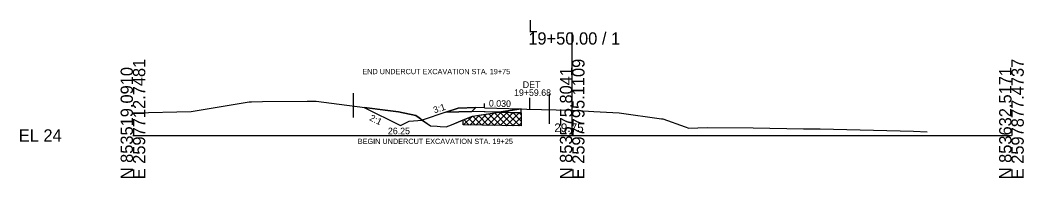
# Model space of a CAD drawing. Extents: x -26 to 1203, y -10 to 9526.
# Drawn here: x -25.7 to 202.8, y 9490.3 to 9526.3 of the extents above; entities that cross this region are included whole.
import ezdxf

# ---------------------------------------------------------------- set-up
doc = ezdxf.new("R2010")
doc.units = 0
for name, color, linetype in [('Exist Cross Section Cell', 7, 'Continuous'), ('Exist XS Center Line Elevation Label', 7, 'Continuous'), ('Exist XS Ground Line', 7, 'Continuous'), ('Prop XS Alignment Label', 7, 'Continuous'), ('Prop XS DDE', 7, 'Continuous'), ('Prop XS DDE Earthwork Shape', 7, 'Continuous'), ('Prop XS DDE Elevations', 7, 'Continuous'), ('Prop XS DDE Slope Text', 7, 'Continuous'), ('Prop XS Earthwork Shape', 7, 'Continuous'), ('Prop XS EOT Tick Mark', 7, 'Continuous'), ('Prop XS Exc Vertical Line 1', 7, 'Continuous'), ('Prop XS Exc Vertical Line 2', 7, 'Continuous'), ('Prop XS Finish Grade', 7, 'Continuous'), ('Prop XS Finish Grade Earthwork', 7, 'Continuous'), ('Prop XS Finish Grade Paved Shoulder', 7, 'Continuous'), ('Prop XS Finish Grade Pavement', 7, 'Continuous'), ('Prop XS Pvmt Edge Slope', 7, 'Continuous'), ('Prop XS SE Text', 7, 'Continuous'), ('Prop XS Side Slope Text', 7, 'Continuous'), ('Prop XS Station Labels', 7, 'Continuous'), ('Prop XS Subgrade Earthwork', 7, 'Continuous'), ('Prop XS Undercut Exc', 7, 'Continuous'), ('Prop XS Undercut Exc Hatch', 7, 'Continuous'), ('Scratch_Level_1', 7, 'Continuous')]:
    doc.layers.add(name, color=color, linetype=linetype)

msp = doc.modelspace()

# ---------------------------------------------------------------- linework, layer by layer
at = {"layer": 'Exist Cross Section Cell'}
for p, q in [((100, 9500), (100, 9523.51)), ((0, 9500), (100, 9500)), ((100, 9500), (200, 9500))]:
    msp.add_line(p, q, dxfattribs=at)
at = {"layer": 'Exist XS Ground Line'}
for p, q in [((13.26, 9505.49), (26.43, 9507.64)), ((26.43, 9507.64), (27.01, 9507.7)), ((27.01, 9507.7), (29.49, 9507.73)), ((29.49, 9507.73), (39.69, 9507.84)), ((39.69, 9507.84), (41.72, 9507.78)), ((41.72, 9507.78), (58.03, 9505.69)), ((0, 9505.12), (0.29, 9505.12)), ((0.29, 9505.12), (13.26, 9505.49)), ((58.03, 9505.69), (60.43, 9505.37)), ((60.43, 9505.37), (64.38, 9504.53)), ((77.27, 9504.39), (79.43, 9504.72)), ((79.43, 9504.72), (88.37, 9506.06)), ((88.37, 9506.06), (89.64, 9506.02)), ((89.64, 9506.02), (99.67, 9505.77)), ((99.67, 9505.77), (100, 9505.75)), ((100, 9505.75), (104.89, 9505.49)), ((104.89, 9505.49), (110.73, 9505.18)), ((110.73, 9505.18), (120.33, 9503.82)), ((64.38, 9504.53), (65.15, 9504.01)), ((65.15, 9504.01), (67.77, 9502.18)), ((71.3, 9501.96), (72.49, 9502.42)), ((72.49, 9502.42), (77.27, 9504.39)), ((120.33, 9503.82), (120.65, 9503.78)), ((120.65, 9503.78), (125.72, 9501.95)), ((67.77, 9502.18), (69.25, 9502.08)), ((69.25, 9502.08), (69.97, 9502.03)), ((69.97, 9502.03), (71.3, 9501.96)), ((125.72, 9501.95), (126.54, 9501.67)), ((126.54, 9501.67), (128.59, 9501.76)), ((128.59, 9501.76), (130.81, 9501.82)), ((130.81, 9501.82), (141.2, 9501.71)), ((141.2, 9501.71), (152.66, 9501.53)), ((152.66, 9501.53), (156.49, 9501.5)), ((156.49, 9501.5), (177.69, 9500.95)), ((177.69, 9500.95), (180.78, 9500.85))]:
    msp.add_line(p, q, dxfattribs=at)
at = {"layer": 'Prop XS DDE'}
for p, q in [((52.62, 9506.38), (60.88, 9502.25)), ((60.88, 9502.25), (62.88, 9503.25)), ((62.88, 9503.25), (65.88, 9503.5))]:
    msp.add_line(p, q, dxfattribs=at)
at = {"layer": 'Prop XS DDE Earthwork Shape'}
for p, q in [((58.03, 9505.69), (52.62, 9506.38)), ((52.62, 9506.38), (60.88, 9502.25)), ((60.43, 9505.37), (58.03, 9505.69)), ((64.38, 9504.53), (60.43, 9505.37)), ((60.88, 9502.25), (62.88, 9503.25)), ((62.88, 9503.25), (65.88, 9503.5)), ((65.15, 9504.01), (64.38, 9504.53)), ((65.88, 9503.5), (65.15, 9504.01))]:
    msp.add_line(p, q, dxfattribs=at)
at = {"layer": 'Prop XS Earthwork Shape'}
for points in [[(77.18, 9505.47), (71.2, 9505.27), (65.88, 9503.5), (67.77, 9502.18), (69.25, 9502.08), (69.97, 9502.03), (71.3, 9501.96), (72.49, 9502.42), (75.18, 9503.53), (77.27, 9504.39), (79.43, 9504.72), (83.3, 9505.3)], [(75.18, 9502.4), (75.18, 9503.53), (77.27, 9504.39), (79.43, 9504.72), (83.3, 9505.3), (88.37, 9505.16), (88.37, 9502.16)], [(88.37, 9505.16), (88.37, 9506.06), (83.3, 9505.3)]]:
    msp.add_lwpolyline(points, close=True, dxfattribs=at)
at = {"layer": 'Prop XS EOT Tick Mark'}
msp.add_line((80.07, 9506.3), (80.07, 9507.3), dxfattribs=at)
at = {"layer": 'Prop XS Exc Vertical Line 1'}
msp.add_line((50.11, 9509.65), (50.11, 9504.07), dxfattribs=at)
at = {"layer": 'Prop XS Exc Vertical Line 2'}
msp.add_line((94.75, 9509.5), (94.75, 9502.68), dxfattribs=at)
at = {"layer": 'Prop XS Finish Grade'}
for p in [(71.2, 9505.27), (78.07, 9506.36)]:
    msp.add_line(p, (74.07, 9506.23), dxfattribs=at)
at = {"layer": 'Prop XS Finish Grade Earthwork'}
msp.add_line((71.2, 9505.27), (65.88, 9503.5), dxfattribs=at)
at = {"layer": 'Prop XS Finish Grade Paved Shoulder'}
msp.add_line((80.07, 9506.3), (78.07, 9506.36), dxfattribs=at)
at = {"layer": 'Prop XS Finish Grade Pavement'}
msp.add_line((80.07, 9506.3), (88.37, 9506.06), dxfattribs=at)
at = {"layer": 'Prop XS Pvmt Edge Slope'}
msp.add_line((78.07, 9506.36), (77.18, 9505.47), dxfattribs=at)
at = {"layer": 'Prop XS Side Slope Text'}
msp.add_line((90.25, 9508.6), (90.25, 9506.08), dxfattribs=at)
at = {"layer": 'Prop XS Subgrade Earthwork'}
for p, q in [((77.18, 9505.47), (71.2, 9505.27)), ((88.37, 9505.16), (77.18, 9505.47)), ((88.37, 9505.16), (88.37, 9506.06))]:
    msp.add_line(p, q, dxfattribs=at)
at = {"layer": 'Prop XS Undercut Exc'}
for p, q in [((88.37, 9505.16), (88.37, 9502.16)), ((75.18, 9502.4), (75.18, 9503.53)), ((88.37, 9502.16), (75.18, 9502.4))]:
    msp.add_line(p, q, dxfattribs=at)
at = {"layer": 'Prop XS Undercut Exc Hatch'}
for p, q in [((78.05, 9502.35), (80.6, 9504.89)), ((79.44, 9502.32), (82.26, 9505.14)), ((79.82, 9504.77), (82.33, 9502.27)), ((80.83, 9502.3), (83.82, 9505.28)), ((81.05, 9504.96), (83.77, 9502.24)), ((82.22, 9502.27), (85.19, 9505.24)), ((82.28, 9505.14), (85.21, 9502.21)), ((83.55, 9505.29), (86.65, 9502.19)), ((83.61, 9502.24), (86.57, 9505.21)), ((85, 9505.25), (88.09, 9502.16)), ((85, 9502.22), (87.94, 9505.17)), ((86.46, 9505.21), (88.37, 9503.29)), ((87.91, 9505.17), (88.37, 9504.71)), ((75.28, 9502.4), (77.27, 9504.39)), ((75.34, 9503.6), (76.56, 9502.38)), ((76.34, 9504.01), (78, 9502.35)), ((76.67, 9502.37), (78.93, 9504.64)), ((77.36, 9504.41), (79.44, 9502.32)), ((78.59, 9504.59), (80.88, 9502.3)), ((86.38, 9502.19), (88.37, 9504.18)), ((87.77, 9502.17), (88.37, 9502.77))]:
    msp.add_line(p, q, dxfattribs=at)
msp.add_lwpolyline([(88.37, 9502.16), (75.18, 9502.4), (75.18, 9503.53), (77.27, 9504.39), (83.3, 9505.3), (88.37, 9505.16)], close=True, dxfattribs=at)
at = {"layer": 'Scratch_Level_1'}
for points in [[(77.18, 9505.47), (71.2, 9505.27), (74.07, 9506.23), (78.07, 9506.36)], [(78.07, 9506.36), (74.07, 9506.23), (71.2, 9505.27), (77.18, 9505.47)]]:
    msp.add_lwpolyline(points, close=True, dxfattribs=at)

# ---------------------------------------------------------------- texts
at = {"layer": 'Exist Cross Section Cell'}
for s, p in [('L', (90, 9523.51)), ('19+50.00 / 1', (90, 9520.71)), ('EL 24', (-26, 9498.6))]:
    msp.add_text(s, height=2.8, dxfattribs=at).set_placement(p)
for s, p in [('E 2597712.7481', (2.8, 9490)), ('E 2597795.1109', (102.8, 9490)), ('E 2597877.4737', (202.8, 9490)), ('N 853519.0910', (0, 9490)), ('N 853575.8041', (100, 9490)), ('N 853632.5171', (200, 9490))]:
    msp.add_text(s, height=2.8, rotation=90, dxfattribs=at).set_placement(p)
at = {"layer": 'Exist XS Center Line Elevation Label'}
msp.add_text('29.75', height=2, dxfattribs=at).set_placement((95.93, 9500.75))
at = {"layer": 'Prop XS Alignment Label'}
msp.add_text('DET', height=1.5, dxfattribs=at).set_placement((88.75, 9510.83))
at = {"layer": 'Prop XS DDE Elevations'}
msp.add_text('26.25', height=1.5, dxfattribs=at).set_placement((58.05, 9500.28))
at = {"layer": 'Prop XS DDE Slope Text'}
msp.add_text('2:1', height=1.5, rotation=333.4349, dxfattribs=at).set_placement((53.71, 9503.52))
at = {"layer": 'Prop XS SE Text'}
msp.add_text('0.030', height=1.5, rotation=358.4069, dxfattribs=at).set_placement((81.02, 9506.61))
at = {"layer": 'Prop XS Side Slope Text'}
msp.add_text('3:1', height=1.5, rotation=18.4349, dxfattribs=at).set_placement((68.65, 9505.02))
at = {"layer": 'Prop XS Station Labels'}
msp.add_text('19+59.68', height=1.5, dxfattribs=at).set_placement((86.76, 9509.01))
at = {"layer": 'Prop XS Undercut Exc Hatch'}
for s, p in [('END UNDERCUT EXCAVATION STA. 19+75', (52.23, 9513.97)), ('BEGIN UNDERCUT EXCAVATION STA. 19+25', (51.19, 9498.06))]:
    msp.add_text(s, height=1.2, dxfattribs=at).set_placement(p)

doc.saveas('drawing.dxf')
